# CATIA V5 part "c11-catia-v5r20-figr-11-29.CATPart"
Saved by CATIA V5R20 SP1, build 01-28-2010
Part number: Part1
Bounding box of the stored display mesh (mm): x -120 to 40, y -443 to 443, z -443 to 443
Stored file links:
  D:\v5_r20\psrt_files_downloaded\c11\c11-catia-v5r20-figr-11-29.CATPart
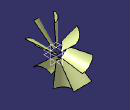
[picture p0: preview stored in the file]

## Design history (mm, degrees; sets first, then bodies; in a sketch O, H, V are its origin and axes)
Set1
  Plane1: type Offset, RefPlane xy-plane, Offset 443
  Sketch1 on Plane1, origin (0, 0, 443), H (1, 0, 0), V (0, 1, 0)
    arc A1 centre (51.3551, -160.9813) radius 171.358 from (40, 10) to (-120, -160) ccw
  Loft1: Sections (Sketch3; Sketch1)
  Sketch2 on zx-plane, origin (0, 0, 0), H (-1, 0, 0), V (0, 0, 1)
    line L1 (-270, 0) -> (280, 0)
    point P1 (-270, 0)
    coincidence: P1 H
    horizontal: L1 H
  Rotate1: ToTransfor Loft1, Axis Sketch2, Angle 45
  Rotate2: ToTransfor Loft1, Axis Sketch2, Angle 90 {= Rotate1.Angle * 2}
  Rotate3: ToTransfor Loft1, Axis Sketch2, Angle 135 {= Rotate1.Angle * 3}
  Rotate4: ToTransfor Loft1, Axis Sketch2, Angle 180 {= Rotate1.Angle * 4}
  Rotate5: ToTransfor Loft1, Axis Sketch2, Angle 225 {= Rotate1.Angle * 5}
  Rotate6: ToTransfor Loft1, Axis Sketch2, Angle 270 {= Rotate1.Angle * 6}
  Rotate7: ToTransfor Loft1, Axis Sketch2, Angle 315 {= Rotate1.Angle * 7}
  Rotate8: ToTransfor Loft1, Axis Sketch2, Angle 360 {= Rotate1.Angle * 8}
  Rotate9: ToTransfor Loft1, Axis Sketch2, Angle 405 {= Rotate1.Angle * 9}
Body1 (main body)
  Sketch3 on Plane2, origin (0, 0, 67), H (1, 0, 0), V (0, 1, 0)
    point P1 (-100, 0)
    arc A1 centre (50, -150) radius 158.1139 from (0, 0) to (-100, -100) ccw
Set2
  Plane2: type Offset, RefPlane xy-plane, Offset 67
